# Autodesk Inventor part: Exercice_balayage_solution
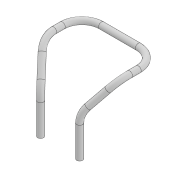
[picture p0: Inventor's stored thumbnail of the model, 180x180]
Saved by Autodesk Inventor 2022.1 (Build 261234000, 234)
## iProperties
Created: 2021-06
Part Number: Exercice_balayage_solution
Material: Générique
Document SubType Name: Modeling
Designer: Fabian
Density: 1 g/cm^3
Appearance: Par défaut
Mass: 130.31 g
Surface Area: 351.028 cm^2
Volume: 130.31 cm^3
Author: Fabian
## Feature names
1. Balayage1
## Parameters: d12 = 45 deg, d14 = 0, d15 = 45 deg, d19 = 15 mm, d20 = 0, d21 = 0
